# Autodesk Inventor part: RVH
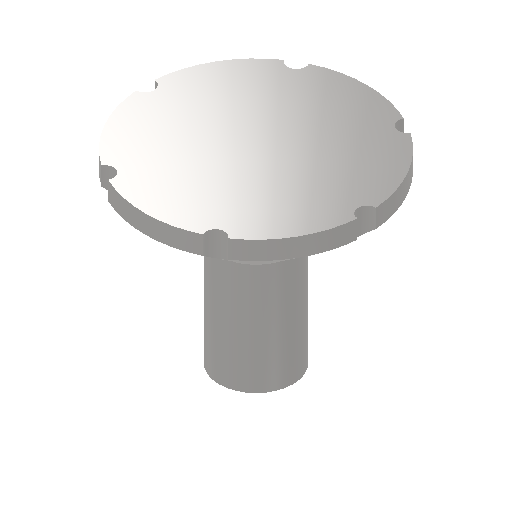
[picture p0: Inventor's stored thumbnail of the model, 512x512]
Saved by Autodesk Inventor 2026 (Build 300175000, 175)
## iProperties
Created: 2004-09
Part Number: RVH
Document SubType Name: Modeling
Designer: Lars Bertram Pedersen
Manufacturer: Standard
Standards Organization: Custom
Material: Steel, Mild
Density: 7.85 g/cm^3
Appearance: Semi-Polished
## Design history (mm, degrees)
revolve "Revolution1" stored, may be unused: angle "d5" = 90 deg
sketch "Sketch2"
  geometry: C1 r 5 at (0, 60); 1 further point
  constraints: 2 vertical alignment, 1 centre point, 1 other
  dimensions: "d7" = 10 diameter of C1
extrude "Extrusion1" cut sketch "Sketch2" extent not by distance; stored distance "d8" = 10; taper "d9" = 0 deg
pattern_circular "Circular Pattern1" dims angle "d12" = 360 deg
body "Solid1"
sketch "Sketch1"
  geometry: L1 (-99.444, 138.194)-(-39.444, 138.194); L2 (-39.444, 138.194)-(-39.444, 128.194); L3 (-39.444, 128.194)-(-79.444, 98.194); L4 (-79.444, 98.194)-(-79.444, 38.194); L5 (-79.444, 38.194)-(-99.444, 38.194); L6 (-99.444, 38.194)-(-99.444, 138.194)
  constraints: 12 end point, 3 parallel, 1 horizontal, 1 perpendicular
  dimensions: "d0" = 10 distance of L1.end L2.end; "d1" = 60 distance of L1.start L1.end; "d2" = 20 distance of L4.end L5.end; "d3" = 60 distance of L3.end L4.end; "d4" = 100 distance of L5.end L1.start
